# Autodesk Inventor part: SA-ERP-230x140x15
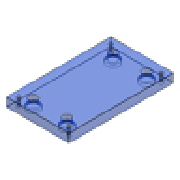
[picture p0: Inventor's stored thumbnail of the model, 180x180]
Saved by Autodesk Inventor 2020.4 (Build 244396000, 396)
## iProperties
Created: 2019-01
Part Number: SA-ERP-230x140x15
Material: S 55 C
Description: Ejector Retainer Plate
Document SubType Name: Modeling
Designer: mel
Standard Revision: 1
Manufacturer: FUTABA
Language: fr-FR
Size Designation: 230x140x15
Categories: <MemberInstance><Categories><Category DisplayName="Moule" InternalName="349578f2-f4d4-4954-8c09-8e99297a61c0" Mnemonic="MOLD"><Category DisplayName="Plaque de m
Density: 7.85 g/cm^3
Appearance: Clear - Blue
Author: mel
IsCustomPart: 1
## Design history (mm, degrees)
sketch "Sketch1"
  geometry: L1 (-70, 115)-(70, 115); L2 (70, 115)-(70, -115); L3 (70, -115)-(-70, -115); L4 (-70, -115)-(-70, 115); 5 further points
  constraints: 8 end point, 2 midpoint, 2 parallel, 1 horizontal, 1 horizontal alignment, 1 perpendicular, 1 vertical alignment
  dimensions: "d84" = 140 distance between parallel lines of L2 L4 (= W_); "d85" = 230 distance between parallel lines of L3 L1 (= L); "d86" = 60 horizontal distance of point (0, 0) point (-60, 105) (= 0.5 x S2_W); "d87" = 105 vertical distance of point (0, 0) point (-60, 105) (= 0.5 x S2_L); "d88" = 53 horizontal distance of point (0, 0) point (-53, 90) (= 0.5 x RP_W); "d89" = 90 vertical distance of point (0, 0) point (-53, 90) (= 0.5 x RP_L)
extrude "Extrusion1" new body sketch "Sketch1" distance "d20" = 15 (= H_); taper "d30" = 0 deg
hole "Hole1" sketch "Sketch1" diameter "d90" = 6.647; stored, may be unused: countersink angle "d94" = 90 deg, drill point angle "d96" = 0 deg; dims "d91" = 6, "d92" = 4, "d93" = 2, "d95" = 15 (= H_)
pattern_linear "Rectangular Pattern1" dims "d99" = 210 (computed from S2_L, Nl), "d102" = 120 (computed from S2_W, Nw)
hole "Hole2" sketch "Sketch1" diameter "d103" = 15 (= RP_d1); stored, may be unused: countersink angle "d107" = 90 deg, drill point angle "d109" = 0 deg; dims "d104" = 6, "d105" = 21 (= RP_d2), "d106" = 4 (= RP_k), "d108" = 15 (= H_)
pattern_linear "Rectangular Pattern2" dims "d112" = 180 (computed from RP_L, Nl), "d115" = 106 (computed from RP_W, Nw)
chamfer "Chamfer1" distance "d116" = 0.5; stored, may be unused: second distance "d117" = 2, angle "d118" = 45 deg
body "Solid1"
other parameters: "L" = 230 [user parameter; used in 1 equation term], "W_" = 140 [user parameter; used in 1 equation term], "H_" = 15 [user parameter; used in 3 equation terms], "RP_k" = 4 [user parameter; used in 1 equation term], "RP_d1" = 15 [user parameter; used in 1 equation term], "RP_d2" = 21 [user parameter; used in 1 equation term], "RP_W" = 106 [user parameter; used in 2 equation terms]
